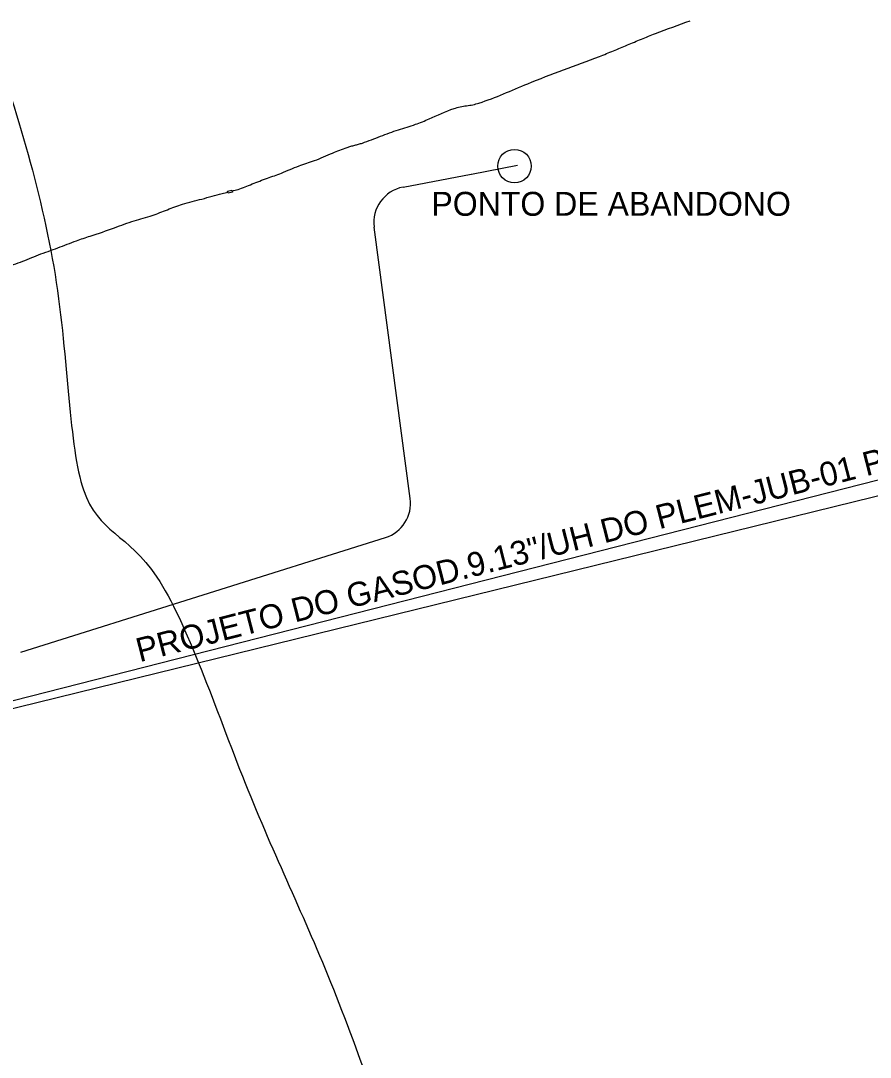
# Model space of a CAD drawing. Extents: x 387828 to 391861, y 7650362 to 7652502.
# Drawn here: x 388497 to 389207, y 7651637 to 7652502 of the extents above; entities that cross this region are included whole.
import ezdxf

# ---------------------------------------------------------------- set-up
doc = ezdxf.new("R2010")
doc.units = 0
for name, color, linetype in [('Batimetria', 7, 'Continuous'), ('Blocos de producao br', 7, 'Continuous'), ('Coral', 7, 'Continuous'), ('Dutos flexiveis', 7, 'Continuous'), ('Variacoes de flexivel', 7, 'Continuous')]:
    doc.layers.add(name, color=color, linetype=linetype)

msp = doc.modelspace()

# ---------------------------------------------------------------- linework, layer by layer
at = {"layer": 'Batimetria'}
msp.add_open_spline([(388468.4, 7652502.5), (388491.33, 7652433.56), (388537.31, 7652290.95), (388537.31, 7652074.68), (388610.97, 7652074.68), (388684.62, 7651853.68), (388758.28, 7651706.18), (388831.94, 7651485.18), (388905.56, 7651264.18), (388905.56, 7651264.18), (388905.56, 7651043.18), (388979.22, 7650822.18), (388979.22, 7650601.17), (388914.31, 7650471.2), (388907.12, 7650390.61), (388902.85, 7650362.31)], degree=3, dxfattribs=at)
at = {"layer": 'Blocos de producao br'}
msp.add_lwpolyline([(388669.9, 7652360.28), (388673.46, 7652361.15), (388673.9, 7652359.37), (388670.33, 7652358.5)], close=True, dxfattribs=at)
at = {"layer": 'Dutos flexiveis'}
for points in [[(388673.67, 7652360.31), (388678.67, 7652361.69), (388690.42, 7652366.2), (388703.2, 7652371.01), (388714.89, 7652375.35), (388729.57, 7652381.31), (388742.44, 7652385.68), (388757.63, 7652392.05), (388769.73, 7652396.74), (388772.89, 7652397.73), (388776.11, 7652398.55), (388779.32, 7652399.38), (388782.48, 7652400.37), (388797.63, 7652406.02), (388812.62, 7652411.44), (388826.87, 7652416), (388838.22, 7652420.56), (388859.09, 7652429.2), (388864.18, 7652430.68), (388869.45, 7652431.53), (388874.73, 7652432.37), (388879.84, 7652433.78), (388920.57, 7652449.93), (388980.45, 7652472.7), (388992.15, 7652477.4), (389003.8, 7652482.27), (389015.45, 7652487.12), (389027.17, 7652491.79), (389056.33, 7652502.5)], [(387976.21, 7652241.68), (387983.68, 7652241.88), (388015.88, 7652242.87), (388050.95, 7652245.62), (388086.03, 7652247.13), (388107.67, 7652249.04), (388130.02, 7652251.49), (388151.29, 7652253.03), (388180.93, 7652255.31), (388197.36, 7652257.17), (388212.41, 7652258.62), (388217.46, 7652259.36), (388222.49, 7652260.29), (388232.57, 7652262), (388252.82, 7652264.5), (388279.47, 7652267.72), (388297.81, 7652270.08), (388313.8, 7652272.09), (388334.72, 7652276.53), (388353.81, 7652279.73), (388366.91, 7652282.4), (388383.71, 7652283.04), (388395.22, 7652283.71), (388399.27, 7652283.4), (388403.28, 7652282.52), (388407.3, 7652281.59), (388411.35, 7652281.11), (388426.16, 7652281.44), (388436.14, 7652281.04), (388447.31, 7652283.96), (388468.07, 7652290.69), (388481.58, 7652295.67), (388496.96, 7652300.96), (388512.04, 7652306.98), (388528.2, 7652312.87), (388543.73, 7652318.8), (388555.2, 7652322.71), (388575.49, 7652329.61), (388591.91, 7652335.5), (388607.07, 7652340), (388613.38, 7652342.26), (388619.63, 7652344.72), (388632.27, 7652349.21), (388648.46, 7652353.65), (388665.44, 7652358.15), (388670.11, 7652359.37)]]:
    msp.add_spline(points, degree=3, dxfattribs=at)
at = {"layer": 'Variacoes de flexivel'}
for p, q in [((388873.57, 7652374.39), (388911.91, 7652381.97)), ((388816.49, 7652363.58), (388873.33, 7652374.35)), ((388822.48, 7652103.61), (388792.33, 7652330.14)), ((388291.88, 7651884.09), (389548.16, 7652204.74)), ((388291.81, 7651879.63), (389557.05, 7652190.49)), ((388497.19, 7651975.2), (388801.75, 7652071.03))]:
    msp.add_line(p, q, dxfattribs=at)
msp.add_circle((388909.54, 7652381.09), 14, dxfattribs=at)
for centre, start, end in [((388867.75, 7652403.82), 280.72539, 281.18632), ((388822.07, 7652334.1), 100.72539, 187.5816), ((388792.75, 7652099.65), 287.46737, 7.5816)]:
    msp.add_arc(centre, 30, start, end, dxfattribs=at)

# ---------------------------------------------------------------- texts
at = {"layer": 'Coral'}
msp.add_text('PONTO DE ABANDONO', height=20, dxfattribs=at).set_placement((388840.14, 7652339.63))
msp.add_text('PROJETO DO GASOD.9.13"/UH DO PLEM-JUB-01 P/P-57 S/PREVISÃO', height=19.9999, rotation=14.35873, dxfattribs=at).set_placement((388596.51, 7651966.81))

doc.saveas('drawing.dxf')
